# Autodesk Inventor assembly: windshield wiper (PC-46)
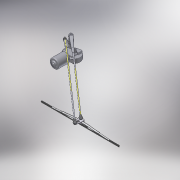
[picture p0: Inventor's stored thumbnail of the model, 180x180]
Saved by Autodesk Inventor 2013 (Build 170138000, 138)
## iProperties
Shininess: 20.0
Length Units: 11269
Angle Units: 11279
Time Units: 11290
Mass Units: 11283
Length Display Precision: 3
Angle Display Precision: 2
Created: 2002-04
Part Number: windshield wiper (PC-46)
Document SubType Name: Assembly
Designer: =<Author>
Description: =<Part Number>
Density: 0.0
Volumn: 0.0
Area: 0.0
PropertySet Name: Model Information
Control State: 0
Master: False
Checked Out: True
Checked Out Date: 2008-10-15
Last Check In Date: 2008-10-15
Author: LAlexey
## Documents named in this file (16)
- D:\_Workspace\Dropbox\Launch 2013\LaunchFolder\Dataset\Front Loader\Data\Assy, Cab\windshield wiper (PC-46).iam
- D:\_Workspace\Dropbox\Launch 2013\LaunchFolder\Dataset\Front Loader\Data\Assy, Cab\nut.ipt
- D:\_Workspace\Dropbox\Launch 2013\LaunchFolder\Dataset\Front Loader\Data\Assy, Cab\nozzle 1.ipt
- D:\_Workspace\Dropbox\Launch 2013\LaunchFolder\Dataset\Front Loader\Data\Assy, Cab\napravlajushaja 1.ipt
- D:\_Workspace\Dropbox\Launch 2013\LaunchFolder\Dataset\Front Loader\Data\Assy, Cab\leash.ipt
- D:\_Workspace\Dropbox\Launch 2013\LaunchFolder\Dataset\Front Loader\Data\Assy, Cab\hinge.ipt
- D:\_Workspace\Dropbox\Launch 2013\LaunchFolder\Dataset\Front Loader\Data\Assy, Cab\stamped.ipt
- D:\_Workspace\Dropbox\Launch 2013\LaunchFolder\Dataset\Front Loader\Data\Assy, Cab\trapezoid.ipt
- D:\_Workspace\Dropbox\Launch 2013\LaunchFolder\Dataset\Front Loader\Data\Assy, Cab\Slotted sleeve.ipt
- D:\_Workspace\Dropbox\Launch 2013\LaunchFolder\Dataset\Front Loader\Data\Assy, Cab\drive.ipt
- D:\_Workspace\Dropbox\Launch 2013\LaunchFolder\Dataset\Front Loader\Data\Assy, Cab\washer.ipt
- D:\_Workspace\Dropbox\Launch 2013\LaunchFolder\Dataset\Front Loader\Data\Assy, Cab\base brush.ipt
- D:\_Workspace\Dropbox\Launch 2013\LaunchFolder\Dataset\Front Loader\Data\Assy, Cab\base brush Mullen.ipt
- D:\_Workspace\Dropbox\Launch 2013\LaunchFolder\Dataset\Front Loader\Data\Assy, Cab\blade spring L=700.ipt
- D:\_Workspace\Dropbox\Launch 2013\LaunchFolder\Dataset\Front Loader\Data\Assy, Cab\band L=700.ipt
- D:\_Workspace\Dropbox\Launch 2013\LaunchFolder\Dataset\Front Loader\Data\Assy, Cab\rubber L = 650.ipt
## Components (18 placed, 15 different names)
1. nut:1 — Insert:2, Insert:3
2. nut:2 — Insert:4
3. nozzle 1:1 — Insert:7, Insert:10, Angle:4
4. nozzle 1:2 — Insert:8, Insert:9
5. napravlajushaja 1:1 — Insert:5, Mate:9, Angle:1, Mate:15, Insert:12
6. band L=700:1 — Insert:10, Mate:12, Mate:13, Mate:14, Angle:4
7. blade spring L=700:1 — Mate:9, Insert:9, Mate:15, Insert:12
8. leash:1 — Insert:3, Mate:1, Insert:4, Mate:10
9. hinge:1 — Insert:6, Mate:10
10. stamped:1 — Insert:6, Mate:12, Mate:13, Mate:14
11. trapezoid:1 — Insert:7, Insert:8, Insert:11
12. Slotted sleeve:1 — Mate:2, Insert:5, Angle:1, Flush:2, Angle:5
13. drive:1 — Insert:1, Mate:1, Mate:2, Flush:2, Angle:3, Angle:5
14. washer:1 — Insert:1, Insert:2
15. base brush Mullen:1 — Mate:3, Mate:4, Mate:7, Mate:8, Flush:1, Angle:2
16. base brush Mullen:2 — Mate:5, Mate:6, Angle:2, Mate:11
17. rubber L = 650:1 — Mate:7, Mate:8, Flush:1, Mate:11, Angle:3
18. base brush:1 — Mate:3, Mate:4, Mate:5, Mate:6, Insert:11
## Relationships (34: Mate 15, Insert 12, Angle 5, Flush 2)
- Insert:1: drive:1 ↔ washer:1
- Insert:2: nut:1 ↔ washer:1
- Insert:3: nut:1 ↔ leash:1
- Mate:1: leash:1 ↔ drive:1
- Mate:2: Slotted sleeve:1 ↔ drive:1
- Insert:4: nut:2 ↔ leash:1
- Insert:5: napravlajushaja 1:1 ↔ Slotted sleeve:1
- Insert:6: hinge:1 ↔ stamped:1
- Mate:3: base brush Mullen:1 ↔ base brush:1
- Mate:4: base brush Mullen:1 ↔ base brush:1
- Mate:5: base brush Mullen:2 ↔ base brush:1
- Mate:6: base brush Mullen:2 ↔ base brush:1
- Mate:7: base brush Mullen:1 ↔ rubber L = 650:1
- Mate:8: base brush Mullen:1 ↔ rubber L = 650:1
- Flush:1: base brush Mullen:1 ↔ rubber L = 650:1
- Mate:9: napravlajushaja 1:1 ↔ blade spring L=700:1
- Angle:1: napravlajushaja 1:1 ↔ Slotted sleeve:1
- Mate:10: leash:1 ↔ hinge:1
- Angle:2: base brush Mullen:1 ↔ base brush Mullen:2
- Mate:11: base brush Mullen:2 ↔ rubber L = 650:1
- Flush:2: Slotted sleeve:1 ↔ drive:1
- Insert:7: nozzle 1:1 ↔ trapezoid:1
- Insert:8: nozzle 1:2 ↔ trapezoid:1
- Insert:9: nozzle 1:2 ↔ blade spring L=700:1
- Insert:10: nozzle 1:1 ↔ band L=700:1
- Insert:11: trapezoid:1 ↔ base brush:1
- Mate:12: band L=700:1 ↔ stamped:1
- Mate:13: band L=700:1 ↔ stamped:1
- Mate:14: band L=700:1 ↔ stamped:1
- Angle:3: drive:1 ↔ rubber L = 650:1
- Angle:4: nozzle 1:1 ↔ band L=700:1
- Angle:5: Slotted sleeve:1 ↔ drive:1
- Mate:15: napravlajushaja 1:1 ↔ blade spring L=700:1
- Insert:12: napravlajushaja 1:1 ↔ blade spring L=700:1
